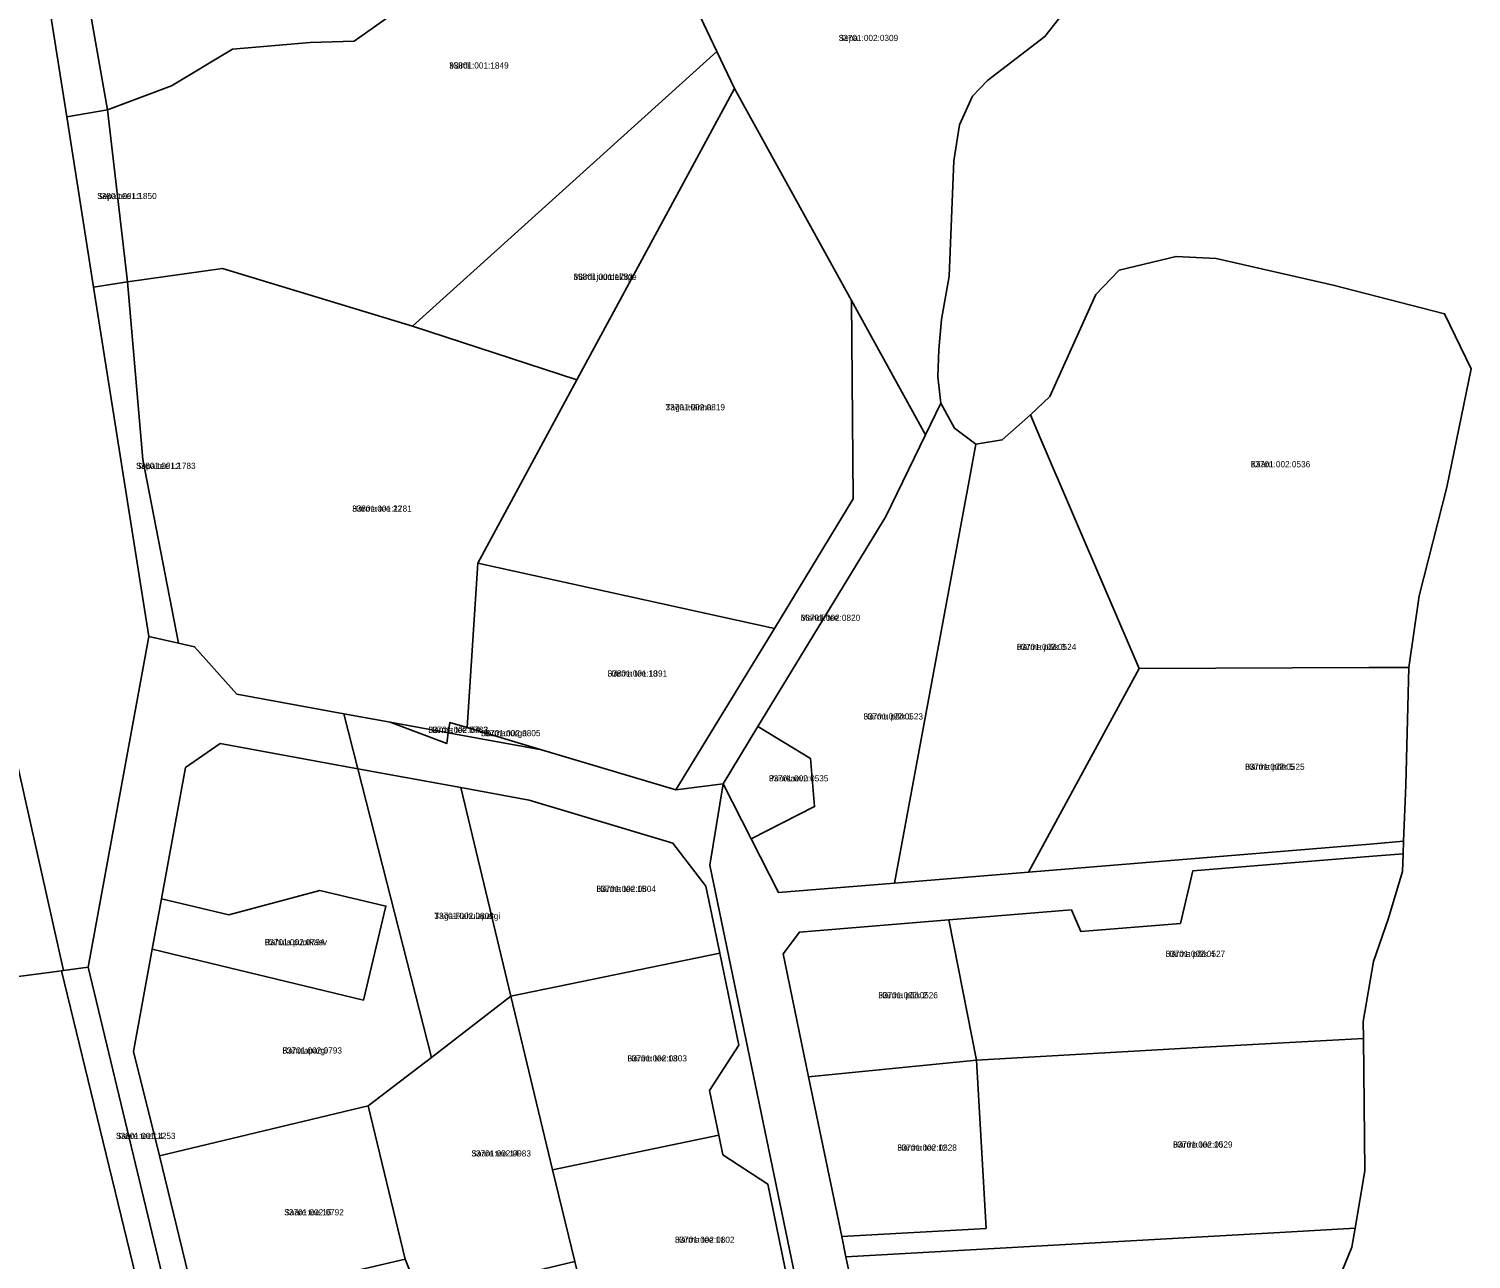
# Model space of a CAD drawing. Extents: x 551583 to 585220, y 6539942 to 6568852.
# Drawn here: x 562222 to 562573.6, y 6563344.4 to 6563644.2 of the extents above; entities that cross this region are included whole.
import ezdxf

# ---------------------------------------------------------------- set-up
doc = ezdxf.new("R2010")
doc.units = 0
for name, color, linetype in [('L_AADRESS', 7, 'Continuous'), ('PIIR', 7, 'Continuous'), ('TUNNUS', 7, 'Continuous')]:
    doc.layers.add(name, color=color, linetype=linetype)

msp = doc.modelspace()

# ---------------------------------------------------------------- linework, layer by layer
at = {"layer": 'PIIR'}
for points in [[(562354.49, 6563697.4), (562344.75, 6563682.99), (562339.86, 6563661.51), (562318.23, 6563653.24), (562301.29, 6563641.22), (562290.54, 6563640.92), (562271.64, 6563639.27), (562256.74, 6563630.38), (562241.19, 6563624.49), (562233.56, 6563667.88), (562222.87, 6563726.58), (562224.71, 6563726.86), (562232.53, 6563731.61), (562239.73, 6563734.1), (562250.09, 6563734.01), (562258.82, 6563731.69), (562271.01, 6563726.63), (562282.4, 6563734.26), (562335.99, 6563723.46), (562345.48, 6563721.51), (562348.03, 6563712.15), (562350.84, 6563703.83), (562353.41, 6563698.69)], [(562102.96, 6563730.93), (562219.16, 6563699.18), (562231.26, 6563622.76), (562237.77, 6563581.31), (562251.23, 6563496.16), (562236.48, 6563415.55), (562230.44, 6563414.74), (562216.8, 6563475.7), (562178.98, 6563464.77), (562174.79, 6563493.02), (562133.49, 6563484.2), (562132.64, 6563490.94), (562114.12, 6563642.35)], [(562218.36, 6563704.55), (562215.05, 6563725.41), (562222.87, 6563726.58), (562233.56, 6563667.88), (562241.19, 6563624.49), (562231.26, 6563622.76), (562219.16, 6563699.18)], [(562269.17, 6563585.81), (562246.04, 6563582.57), (562241.19, 6563624.49), (562256.74, 6563630.38), (562271.64, 6563639.27), (562290.54, 6563640.92), (562301.29, 6563641.22), (562318.23, 6563653.24), (562339.86, 6563661.51), (562344.75, 6563682.99), (562354.49, 6563697.4), (562355.36, 6563696.36), (562357.81, 6563694.77), (562360.75, 6563693.67), (562363.44, 6563693.67), (562368.99, 6563682.32), (562389.71, 6563638.69), (562342.91, 6563596.48), (562315.49, 6563571.74)], [(562355.61, 6563558.67), (562315.49, 6563571.74), (562342.91, 6563596.48), (562389.71, 6563638.69), (562394.03, 6563629.71), (562378.91, 6563601.79)], [(562378.91, 6563601.79), (562394.03, 6563629.71), (562422.49, 6563578.05), (562422.94, 6563529.67), (562403.73, 6563498.11), (562331.43, 6563514.02), (562355.61, 6563558.67)], [(562237.77, 6563581.31), (562231.26, 6563622.76), (562241.19, 6563624.49), (562246.04, 6563582.57)], [(562249.78, 6563539.27), (562246.04, 6563582.57), (562269.17, 6563585.81), (562315.49, 6563571.74), (562355.61, 6563558.67), (562331.43, 6563514.02), (562328.81, 6563473.91), (562324.62, 6563475.18), (562324.18, 6563472.66), (562310.09, 6563475.23), (562298.77, 6563477.31), (562272.72, 6563482.06), (562262.4, 6563493.62), (562258.51, 6563494.54)], [(562468.52, 6563544.59), (562466.12, 6563550.19), (562470.83, 6563554.67), (562482.09, 6563579.5), (562487.74, 6563585.39), (562501.66, 6563588.79), (562511.4, 6563588.29), (562539.92, 6563581.75), (562567.11, 6563574.8), (562573.57, 6563561.34), (562567.67, 6563532.55), (562560.88, 6563506.07), (562558.36, 6563488.58), (562548.71, 6563488.54), (562492.65, 6563488.3)], [(562251.23, 6563496.16), (562237.77, 6563581.31), (562246.04, 6563582.57), (562249.78, 6563539.27), (562258.51, 6563494.54)], [(562422.49, 6563578.05), (562440.59, 6563545.3), (562430.92, 6563525.37), (562399.73, 6563474.23), (562391.26, 6563460.22), (562379.68, 6563458.72), (562403.73, 6563498.11), (562422.94, 6563529.67)], [(562440.59, 6563545.3), (562444.33, 6563553.01), (562447.61, 6563546.91), (562452.84, 6563543.02), (562451.61, 6563536.37), (562432.97, 6563436.01), (562404.71, 6563433.69), (562398.06, 6563446.81), (562413.52, 6563454.65), (562412.56, 6563466.42), (562399.73, 6563474.23), (562430.92, 6563525.37)], [(562451.61, 6563536.37), (562452.84, 6563543.02), (562459.27, 6563544.04), (562466.12, 6563550.19), (562468.52, 6563544.59), (562492.65, 6563488.3), (562465.65, 6563438.69), (562432.97, 6563436.01)], [(562328.81, 6563473.91), (562331.43, 6563514.02), (562403.73, 6563498.11), (562379.68, 6563458.72), (562346.92, 6563468.49)], [(562492.65, 6563488.3), (562548.71, 6563488.54), (562558.36, 6563488.58), (562557.61, 6563459.9), (562557.08, 6563446.2), (562549.83, 6563445.61), (562465.65, 6563438.69)], [(562178.98, 6563464.77), (562216.8, 6563475.7), (562230.44, 6563414.74), (562229.93, 6563414.67), (562187.3, 6563409.01)], [(562310.09, 6563475.23), (562324.18, 6563472.66), (562323.85, 6563470.04)], [(562324.62, 6563475.18), (562328.81, 6563473.91), (562346.92, 6563468.49), (562324.18, 6563472.66)], [(562399.73, 6563474.23), (562412.56, 6563466.42), (562413.52, 6563454.65), (562398.06, 6563446.81), (562391.26, 6563460.22)], [(562260.18, 6563464.19), (562268.61, 6563470.03), (562302.16, 6563463.88), (562320.12, 6563393.54), (562304.72, 6563381.71), (562253.87, 6563369.51), (562247.51, 6563394.95), (562252.07, 6563419.89), (562303.56, 6563407.52), (562309.05, 6563430.4), (562292.89, 6563434.24), (562270.76, 6563428.25), (562254.33, 6563432.2)], [(562302.16, 6563463.88), (562327.28, 6563459.29), (562339.51, 6563408.44), (562320.12, 6563393.54)], [(562327.28, 6563459.29), (562343.94, 6563456.24), (562378.99, 6563445.75), (562387.02, 6563435.26), (562390.4, 6563418.97), (562339.51, 6563408.44)], [(562446.25, 6563427.07), (562476.15, 6563429.52), (562478.45, 6563424.19), (562502.71, 6563426.18), (562505.69, 6563438.97), (562549.57, 6563442.57), (562556.97, 6563443.18), (562556.8, 6563438.88), (562553.38, 6563427.2), (562549.79, 6563416.94), (562547.25, 6563402.28), (562547.3, 6563398.18), (562526.27, 6563397), (562505.56, 6563395.84), (562453.01, 6563392.89)], [(562254.33, 6563432.2), (562270.76, 6563428.25), (562292.89, 6563434.24), (562309.05, 6563430.4), (562303.56, 6563407.52), (562252.07, 6563419.89)], [(562409.83, 6563424.07), (562446.25, 6563427.07), (562453.01, 6563392.89), (562412.08, 6563388.81), (562405.86, 6563418.77)], [(562339.51, 6563408.44), (562390.4, 6563418.97), (562395.05, 6563396.54), (562387.92, 6563385.46), (562390.18, 6563374.54), (562349.68, 6563366.14)], [(562158.28, 6563319), (562145.66, 6563403.52), (562187.3, 6563409.01), (562229.93, 6563414.67), (562250.24, 6563331.12), (562248.84, 6563330.94)], [(562250.24, 6563331.12), (562229.93, 6563414.67), (562230.44, 6563414.74), (562236.48, 6563415.55), (562256.56, 6563331.98)], [(562304.72, 6563381.71), (562320.12, 6563393.54), (562339.51, 6563408.44), (562349.68, 6563366.14), (562355.05, 6563343.79), (562334.08, 6563338.75), (562317.56, 6563334.78), (562313.69, 6563344.38)], [(562453.01, 6563392.89), (562505.56, 6563395.84), (562526.27, 6563397), (562547.3, 6563398.18), (562547.68, 6563365.88), (562545.26, 6563351.89), (562526.97, 6563350.86), (562505.05, 6563349.63), (562421.18, 6563344.92), (562420.16, 6563349.87), (562455.32, 6563351.85)], [(562412.08, 6563388.81), (562453.01, 6563392.89), (562455.32, 6563351.85), (562420.16, 6563349.87)], [(562253.87, 6563369.51), (562304.72, 6563381.71), (562313.69, 6563344.38), (562301.24, 6563341.4), (562297.43, 6563335.2), (562269.02, 6563328.37), (562262.97, 6563332.06)], [(562349.68, 6563366.14), (562390.18, 6563374.54), (562391.16, 6563369.82), (562402.09, 6563362.65), (562408.38, 6563332.12), (562360.29, 6563322.16), (562355.05, 6563343.79)], [(562421.18, 6563344.92), (562505.05, 6563349.63), (562526.97, 6563350.86), (562545.26, 6563351.89), (562544.47, 6563347.3), (562534.67, 6563323.25), (562525.22, 6563322.72), (562501.89, 6563321.41), (562427.09, 6563317.21)]]:
    msp.add_lwpolyline(points, close=True, dxfattribs=at)
for points in [[(562473.86, 6563647.76), (562469.68, 6563642.35), (562455.68, 6563631.67), (562451.98, 6563627.82), (562448.89, 6563620.85), (562447.43, 6563612.04), (562446.36, 6563583.99), (562444.48, 6563573.41), (562443.81, 6563566.1), (562443.59, 6563559.39), (562444.33, 6563553.01), (562440.59, 6563545.3), (562422.49, 6563578.05), (562394.03, 6563629.71), (562389.71, 6563638.69), (562368.99, 6563682.32)], [(562534.67, 6563323.25), (562544.47, 6563347.3), (562545.26, 6563351.89), (562547.68, 6563365.88), (562547.3, 6563398.18), (562547.25, 6563402.28), (562549.79, 6563416.94), (562553.38, 6563427.2), (562556.8, 6563438.88), (562556.97, 6563443.18), (562557.08, 6563446.2), (562557.61, 6563459.9), (562558.36, 6563488.58), (562560.88, 6563506.07), (562567.67, 6563532.55), (562573.57, 6563561.34), (562567.11, 6563574.8), (562539.92, 6563581.75), (562511.4, 6563588.29), (562501.66, 6563588.79), (562487.74, 6563585.39), (562482.09, 6563579.5), (562470.83, 6563554.67), (562466.12, 6563550.19), (562459.27, 6563544.04), (562452.84, 6563543.02), (562447.61, 6563546.91), (562444.33, 6563553.01), (562443.59, 6563559.39), (562443.81, 6563566.1), (562444.48, 6563573.41), (562446.36, 6563583.99), (562447.43, 6563612.04), (562448.89, 6563620.85), (562451.98, 6563627.82), (562455.68, 6563631.67), (562469.68, 6563642.35), (562473.86, 6563647.76)], [(562256.56, 6563331.98), (562236.48, 6563415.55), (562250.03, 6563489.47), (562251.23, 6563496.16), (562258.51, 6563494.54), (562262.4, 6563493.62), (562272.72, 6563482.06), (562298.77, 6563477.31), (562302.16, 6563463.88), (562268.61, 6563470.03), (562260.18, 6563464.19), (562254.33, 6563432.2), (562252.07, 6563419.89), (562247.51, 6563394.95), (562253.87, 6563369.51), (562262.97, 6563332.06)], [(562408.38, 6563332.12), (562402.09, 6563362.65), (562391.16, 6563369.82), (562390.18, 6563374.54), (562387.92, 6563385.46), (562395.05, 6563396.54), (562390.4, 6563418.97), (562387.02, 6563435.26), (562378.99, 6563445.75), (562343.94, 6563456.24), (562327.28, 6563459.29), (562302.16, 6563463.88), (562298.77, 6563477.31), (562310.09, 6563475.23), (562323.85, 6563470.04), (562324.18, 6563472.66), (562346.92, 6563468.49), (562379.68, 6563458.72), (562391.26, 6563460.22), (562387.99, 6563440.43), (562412.96, 6563320.08)], [(562412.96, 6563320.08), (562387.99, 6563440.43), (562391.26, 6563460.22), (562398.06, 6563446.81), (562404.71, 6563433.69), (562432.97, 6563436.01), (562465.65, 6563438.69), (562549.83, 6563445.61), (562557.08, 6563446.2), (562556.97, 6563443.18), (562549.57, 6563442.57), (562505.69, 6563438.97), (562502.71, 6563426.18), (562478.45, 6563424.19), (562476.15, 6563429.52), (562446.25, 6563427.07), (562409.83, 6563424.07), (562405.86, 6563418.77), (562412.08, 6563388.81), (562420.16, 6563349.87), (562421.18, 6563344.92), (562427.09, 6563317.21)], [(562301.24, 6563341.4), (562313.69, 6563344.38), (562317.56, 6563334.78)]]:
    msp.add_lwpolyline(points, dxfattribs=at)

# ---------------------------------------------------------------- texts
at = {"layer": 'L_AADRESS'}
for s, p in [('Sepa', (562419.4, 6563641.28)), ('Märdi', (562324.45, 6563634.57)), ('Sepa tee L3', (562238.65, 6563602.75)), ('Märdi juurdelõige', (562354.76, 6563583.06)), ('Taga-Härma', (562377.18, 6563551.27)), ('Sepa tee L2', (562248.14, 6563536.98)), ('Kääru', (562519.84, 6563537.38)), ('Härma tee 22', (562300.82, 6563526.56)), ('Mandli tee', (562410.14, 6563499.96)), ('Härma põik 3', (562462.81, 6563492.84)), ('Härma tee 18', (562363.09, 6563486.37)), ('Härma põik 1', (562425.45, 6563475.9)), ('Härma tee lõik 3', (562319.37, 6563472.64)), ('Härmanurga', (562332.21, 6563471.83)), ('Puurkaevu', (562402.39, 6563460.81)), ('Härma põik 5', (562518.47, 6563463.63)), ('Härma tee 15', (562360.35, 6563433.87)), ('Taga-Rahulapargi', (562320.83, 6563427.28)), ('Rahula puurkaev', (562279.51, 6563420.88)), ('Härma põik 4', (562499.11, 6563418.04)), ('Härma põik 2', (562429.07, 6563407.94)), ('Rahulapargi', (562283.81, 6563394.48)), ('Härma tee 13', (562367.91, 6563392.55)), ('Saare tee L4', (562243.25, 6563373.65)), ('Saare tee 14', (562329.88, 6563369.39)), ('Härma tee 12', (562433.7, 6563370.8)), ('Härma tee 10', (562500.91, 6563371.55)), ('Saare tee 16', (562284.26, 6563355.04)), ('Härma tee 11', (562379.5, 6563348.35))]:
    msp.add_text(s, height=1.5, dxfattribs=at).set_placement(p)
at = {"layer": 'TUNNUS'}
for s, p in [('33701:002:0309', (562419.4, 6563641.28)), ('33801:001:1849', (562324.45, 6563634.57)), ('33801:001:1850', (562238.65, 6563602.75)), ('33801:001:1782', (562354.76, 6563583.06)), ('33701:002:0819', (562377.18, 6563551.27)), ('33801:001:1783', (562248.14, 6563536.98)), ('33701:002:0536', (562519.84, 6563537.38)), ('33801:001:1781', (562300.82, 6563526.56)), ('33701:002:0820', (562410.14, 6563499.96)), ('33701:002:0524', (562462.81, 6563492.84)), ('33801:001:1391', (562363.09, 6563486.37)), ('33701:002:0523', (562425.45, 6563475.9)), ('33701:002:0783', (562319.37, 6563472.64)), ('33701:002:0805', (562332.21, 6563471.83)), ('33701:002:0535', (562402.39, 6563460.81)), ('33701:002:0525', (562518.47, 6563463.63)), ('33701:002:0804', (562360.35, 6563433.87)), ('33701:002:0808', (562320.83, 6563427.28)), ('33701:002:0794', (562279.51, 6563420.88)), ('33701:002:0527', (562499.11, 6563418.04)), ('33701:002:0526', (562429.07, 6563407.94)), ('33701:002:0793', (562283.81, 6563394.48)), ('33701:002:0803', (562367.91, 6563392.55)), ('33801:001:1253', (562243.25, 6563373.65)), ('33701:002:0983', (562329.88, 6563369.39)), ('33701:002:0528', (562433.7, 6563370.8)), ('33701:002:0529', (562500.91, 6563371.55)), ('33701:002:0792', (562284.26, 6563355.04)), ('33701:002:0802', (562379.5, 6563348.35))]:
    msp.add_text(s, height=1.5, dxfattribs=at).set_placement(p)

doc.saveas('drawing.dxf')
